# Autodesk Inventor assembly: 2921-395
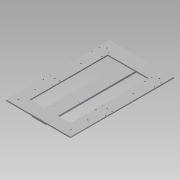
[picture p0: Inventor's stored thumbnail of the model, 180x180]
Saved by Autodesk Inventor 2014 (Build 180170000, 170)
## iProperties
Company: NHTSA/VRTC
Created: 2012-12
Part Number: 2921-395
Document SubType Name: Assembly
Designer: Mike Vanvoorhis
Project: CHILD SIDE IMPACT SLED
Description: BEARING MOUNT PLATE ASS'Y.
Title: Bearing Mount Plate Ass'y.
Subject: Child Side Impact Sled
Author: Dave Walker
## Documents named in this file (5)
- B:\VRTC_DWG\BIO\Non-P572\Child Side-Frontal Impact Sled\Side Impact Sled\Rail Bearing Mount Plate Assembly.iam
- B:\VRTC_DWG\BIO\Non-P572\Child Side-Frontal Impact Sled\Side Impact Sled\Rail_Bearing_Mount_Plate.ipt
- B:\VRTC_DWG\BIO\Non-P572\Child Side-Frontal Impact Sled\Side Impact Sled\Anti_Rebound_Slider_Base.ipt
- B:\VRTC_DWG\BIO\Non-P572\Child Side-Frontal Impact Sled\Side Impact Sled\Anti_Rebound_Slider_DelrinSurface.ipt
- B:\VRTC_DWG\Inventor Support Files\Content Center\en-US\ANSI B18.3(04)\ANSI B18.3 - 10-32 UNF - 0.5(30).ipt
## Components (17 placed, 4 different names)
1. Rail_Bearing_Mount_Plate:1 — Mate:1, Mate:2, Flush:1
2. Anti_Rebound_Slider_Base:1 — Mate:1, Mate:2, Flush:1, Insert:1, Insert:2
3. Anti_Rebound_Slider_DelrinSurface:1 — Insert:1, Insert:2, Insert:3, Insert:4, Insert:5, Insert:6, Insert:7, Insert:8, Insert:9, Insert:10, Insert:11, Insert:12, Insert:13, Insert:14, Insert:15, Insert:16
4. Hexagon Socket Flat Countersunk Head Cap Screw - Inch 10-32 UNF x 0.5:1 — Insert:3
5. Hexagon Socket Flat Countersunk Head Cap Screw - Inch 10-32 UNF x 0.5:2 — Insert:15
6. Hexagon Socket Flat Countersunk Head Cap Screw - Inch 10-32 UNF x 0.5:3 — Insert:12
7. Hexagon Socket Flat Countersunk Head Cap Screw - Inch 10-32 UNF x 0.5:4 — Insert:11
8. Hexagon Socket Flat Countersunk Head Cap Screw - Inch 10-32 UNF x 0.5:5 — Insert:14
9. Hexagon Socket Flat Countersunk Head Cap Screw - Inch 10-32 UNF x 0.5:6 — Insert:16
10. Hexagon Socket Flat Countersunk Head Cap Screw - Inch 10-32 UNF x 0.5:7 — Insert:13
11. Hexagon Socket Flat Countersunk Head Cap Screw - Inch 10-32 UNF x 0.5:8 — Insert:10
12. Hexagon Socket Flat Countersunk Head Cap Screw - Inch 10-32 UNF x 0.5:9 — Insert:9
13. Hexagon Socket Flat Countersunk Head Cap Screw - Inch 10-32 UNF x 0.5:10 — Insert:8
14. Hexagon Socket Flat Countersunk Head Cap Screw - Inch 10-32 UNF x 0.5:11 — Insert:6
15. Hexagon Socket Flat Countersunk Head Cap Screw - Inch 10-32 UNF x 0.5:12 — Insert:4
16. Hexagon Socket Flat Countersunk Head Cap Screw - Inch 10-32 UNF x 0.5:13 — Insert:5
17. Hexagon Socket Flat Countersunk Head Cap Screw - Inch 10-32 UNF x 0.5:14 — Insert:7
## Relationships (19: Insert 16, Mate 2, Flush 1)
- Mate:1: Rail_Bearing_Mount_Plate:1 ↔ Anti_Rebound_Slider_Base:1
- Mate:2: Rail_Bearing_Mount_Plate:1 ↔ Anti_Rebound_Slider_Base:1
- Flush:1: Rail_Bearing_Mount_Plate:1 ↔ Anti_Rebound_Slider_Base:1
- Insert:1: Anti_Rebound_Slider_Base:1 ↔ Anti_Rebound_Slider_DelrinSurface:1
- Insert:2: Anti_Rebound_Slider_Base:1 ↔ Anti_Rebound_Slider_DelrinSurface:1
- Insert:3: Anti_Rebound_Slider_DelrinSurface:1 ↔ Hexagon Socket Flat Countersunk Head Cap Screw - Inch 10-32 UNF x 0.5:1
- Insert:4: Anti_Rebound_Slider_DelrinSurface:1 ↔ Hexagon Socket Flat Countersunk Head Cap Screw - Inch 10-32 UNF x 0.5:12
- Insert:5: Anti_Rebound_Slider_DelrinSurface:1 ↔ Hexagon Socket Flat Countersunk Head Cap Screw - Inch 10-32 UNF x 0.5:13
- Insert:6: Anti_Rebound_Slider_DelrinSurface:1 ↔ Hexagon Socket Flat Countersunk Head Cap Screw - Inch 10-32 UNF x 0.5:11
- Insert:7: Anti_Rebound_Slider_DelrinSurface:1 ↔ Hexagon Socket Flat Countersunk Head Cap Screw - Inch 10-32 UNF x 0.5:14
- Insert:8: Anti_Rebound_Slider_DelrinSurface:1 ↔ Hexagon Socket Flat Countersunk Head Cap Screw - Inch 10-32 UNF x 0.5:10
- Insert:9: Anti_Rebound_Slider_DelrinSurface:1 ↔ Hexagon Socket Flat Countersunk Head Cap Screw - Inch 10-32 UNF x 0.5:9
- Insert:10: Anti_Rebound_Slider_DelrinSurface:1 ↔ Hexagon Socket Flat Countersunk Head Cap Screw - Inch 10-32 UNF x 0.5:8
- Insert:11: Anti_Rebound_Slider_DelrinSurface:1 ↔ Hexagon Socket Flat Countersunk Head Cap Screw - Inch 10-32 UNF x 0.5:4
- Insert:12: Anti_Rebound_Slider_DelrinSurface:1 ↔ Hexagon Socket Flat Countersunk Head Cap Screw - Inch 10-32 UNF x 0.5:3
- Insert:13: Anti_Rebound_Slider_DelrinSurface:1 ↔ Hexagon Socket Flat Countersunk Head Cap Screw - Inch 10-32 UNF x 0.5:7
- Insert:14: Anti_Rebound_Slider_DelrinSurface:1 ↔ Hexagon Socket Flat Countersunk Head Cap Screw - Inch 10-32 UNF x 0.5:5
- Insert:15: Anti_Rebound_Slider_DelrinSurface:1 ↔ Hexagon Socket Flat Countersunk Head Cap Screw - Inch 10-32 UNF x 0.5:2
- Insert:16: Anti_Rebound_Slider_DelrinSurface:1 ↔ Hexagon Socket Flat Countersunk Head Cap Screw - Inch 10-32 UNF x 0.5:6
